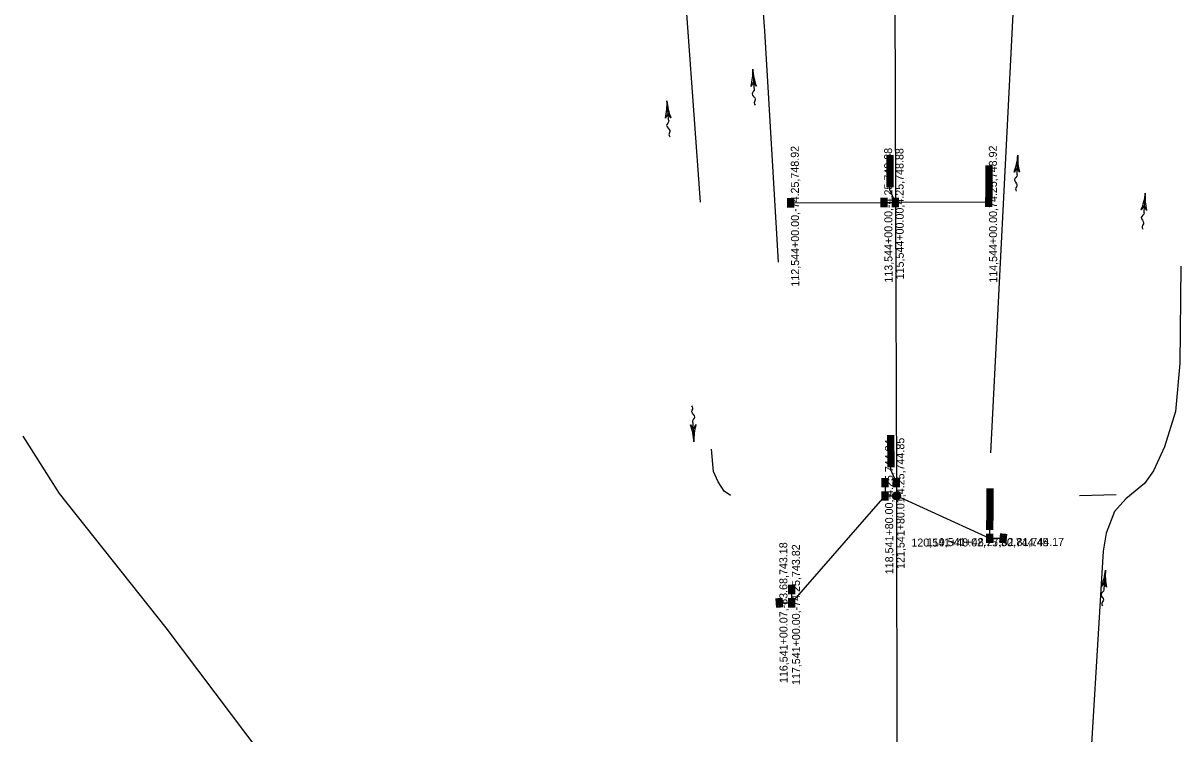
# Model space of a CAD drawing. Extents: x 593481 to 595602, y 151646 to 157396.
# Drawn here: x 593709 to 594578, y 153277 to 153810 of the extents above; entities that cross this region are included whole.
import ezdxf

# ---------------------------------------------------------------- set-up
doc = ezdxf.new("R2010")
doc.units = 0
for name, color, linetype in [('P_ALI_50_Equation', 7, 'Continuous'), ('P_DRN_Flow', 7, 'Continuous'), ('P_DRN_Inlet', 7, 'Continuous'), ('P_DRN_SS_MH', 7, 'Continuous'), ('P_DRN_SS_UG', 7, 'Continuous')]:
    doc.layers.add(name, color=color, linetype=linetype)

msp = doc.modelspace()

# ---------------------------------------------------------------- linework, layer by layer
at = {"layer": 'P_DRN_Flow'}
for p, q in [((594256.49, 153775.14), (594257.31, 153761.03)), ((594192.15, 153751.4), (594193.17, 153737.31)), ((594455.21, 153710.73), (594454.48, 153696.62)), ((594550.81, 153682.25), (594549.67, 153668.17)), ((594212.46, 153495.81), (594211.83, 153509.92)), ((594521.03, 153399.72), (594519.66, 153385.66))]:
    msp.add_line(p, q, dxfattribs=at)
for points in [[(594259.24, 153762.48), (594257.05, 153765.56), (594255.24, 153762.24)], [(594195.07, 153738.78), (594192.85, 153741.83), (594191.08, 153738.49)], [(594456.55, 153697.85), (594454.72, 153701.15), (594452.55, 153698.05)], [(594551.77, 153669.34), (594550.04, 153672.69), (594547.79, 153669.65)], [(594209.88, 153508.5), (594212.03, 153505.39), (594213.88, 153508.68)], [(594521.78, 153386.79), (594520.1, 153390.17), (594517.8, 153387.18)]]:
    msp.add_lwpolyline(points, dxfattribs=at)
for centre, start, end in [((594214.6, 153772.68), 345.59586, 3.35818), ((594298.37, 153777.6), 183.35818, 201.1205), ((594150.31, 153748.39), 346.35512, 4.11744), ((594234, 153754.41), 184.11744, 201.87976), ((594413.31, 153712.89), 339.29398, 357.0563), ((594497.11, 153708.58), 177.0563, 194.81862), ((594508.99, 153685.64), 337.60208, 355.3644), ((594592.63, 153678.86), 175.3644, 193.12672), ((594170.55, 153493.91), 2.58814, 20.35046), ((594254.38, 153497.7), 164.82582, 182.58814), ((594479.27, 153403.79), 336.67264, 354.43496), ((594562.79, 153395.65), 174.43496, 192.19728)]:
    msp.add_arc(centre, 41.96, start, end, dxfattribs=at)
for points in [[(594257.31, 153761.03), (594257.67, 153760.27), (594256.01, 153756.55), (594258.43, 153752.77), (594257.65, 153749.89), (594258.38, 153748.2)], [(594193.17, 153737.31), (594193.54, 153736.55), (594191.92, 153732.81), (594194.39, 153729.06), (594193.66, 153726.17), (594194.41, 153724.49)], [(594454.48, 153696.62), (594454.75, 153695.82), (594452.69, 153692.31), (594454.68, 153688.28), (594453.6, 153685.51), (594454.13, 153683.75)], [(594549.67, 153668.17), (594549.92, 153667.36), (594547.75, 153663.91), (594549.62, 153659.83), (594548.46, 153657.09), (594548.94, 153655.31)], [(594211.83, 153509.92), (594211.48, 153510.69), (594213.19, 153514.38), (594210.82, 153518.2), (594211.64, 153521.07), (594210.93, 153522.77)], [(594519.66, 153385.66), (594519.89, 153384.85), (594517.67, 153381.44), (594519.47, 153377.32), (594518.26, 153374.6), (594518.72, 153372.82)]]:
    msp.add_spline(points, degree=3, dxfattribs=at)
at = {"layer": 'P_DRN_Inlet'}
for p, q in [((594357.04, 153710.77), (594357.12, 153686.77)), ((594357.94, 153710.77), (594358.02, 153686.77)), ((594358.84, 153710.77), (594358.92, 153686.77)), ((594359.74, 153710.78), (594359.82, 153686.78)), ((594360.64, 153710.78), (594360.72, 153686.78)), ((594361.54, 153710.78), (594361.62, 153686.78)), ((594431.31, 153702.96), (594431.38, 153678.96)), ((594432.21, 153702.96), (594432.28, 153678.97)), ((594433.11, 153702.97), (594433.18, 153678.97)), ((594434.01, 153702.97), (594434.08, 153678.97)), ((594434.91, 153702.97), (594434.98, 153678.97)), ((594435.81, 153702.98), (594435.88, 153678.98)), ((594282.91, 153671.57), (594282.89, 153678.44)), ((594283.81, 153671.57), (594283.79, 153678.45)), ((594284.71, 153671.57), (594284.69, 153678.45)), ((594285.61, 153671.58), (594285.59, 153678.45)), ((594286.51, 153671.58), (594286.49, 153678.45)), ((594287.41, 153671.58), (594287.39, 153678.46)), ((594352.91, 153671.78), (594352.89, 153678.66)), ((594353.81, 153671.79), (594353.79, 153678.66)), ((594354.71, 153671.79), (594354.69, 153678.66)), ((594355.61, 153671.79), (594355.59, 153678.67)), ((594356.51, 153671.79), (594356.49, 153678.67)), ((594357.41, 153671.8), (594357.39, 153678.67)), ((594361.41, 153671.81), (594361.39, 153678.68)), ((594362.31, 153671.81), (594362.29, 153678.69)), ((594363.21, 153671.81), (594363.19, 153678.69)), ((594364.11, 153671.82), (594364.09, 153678.69)), ((594365.01, 153671.82), (594364.99, 153678.7)), ((594365.91, 153671.82), (594365.89, 153678.7)), ((594431.41, 153672.02), (594431.39, 153678.9)), ((594432.31, 153672.03), (594432.29, 153678.9)), ((594433.21, 153672.03), (594433.19, 153678.91)), ((594434.11, 153672.03), (594434.09, 153678.91)), ((594435.01, 153672.04), (594434.99, 153678.91)), ((594435.91, 153672.04), (594435.89, 153678.91)), ((594357.64, 153500.78), (594357.7, 153476.78)), ((594358.54, 153500.78), (594358.6, 153476.78)), ((594359.44, 153500.78), (594359.5, 153476.78)), ((594360.34, 153500.79), (594360.4, 153476.79)), ((594361.24, 153500.79), (594361.3, 153476.79)), ((594362.14, 153500.79), (594362.2, 153476.79)), ((594353.49, 153461.79), (594353.48, 153468.66)), ((594354.39, 153461.79), (594354.38, 153468.67)), ((594355.29, 153461.79), (594355.28, 153468.67)), ((594356.19, 153461.8), (594356.18, 153468.67)), ((594357.09, 153461.8), (594357.08, 153468.67)), ((594357.99, 153461.8), (594357.98, 153468.67)), ((594361.99, 153461.81), (594361.98, 153468.69)), ((594362.89, 153461.81), (594362.88, 153468.69)), ((594363.79, 153461.81), (594363.78, 153468.69)), ((594364.69, 153461.82), (594364.68, 153468.69)), ((594365.59, 153461.82), (594365.58, 153468.69)), ((594366.49, 153461.82), (594366.48, 153468.7)), ((594353.52, 153451.79), (594353.5, 153458.66)), ((594354.42, 153451.79), (594354.4, 153458.67)), ((594355.32, 153451.79), (594355.3, 153458.67)), ((594356.22, 153451.79), (594356.2, 153458.67)), ((594357.12, 153451.8), (594357.1, 153458.67)), ((594358.02, 153451.8), (594358, 153458.67)), ((594431.98, 153460.88), (594432.05, 153436.88)), ((594432.88, 153460.88), (594432.95, 153436.88)), ((594433.78, 153460.88), (594433.85, 153436.88)), ((594434.68, 153460.88), (594434.75, 153436.89)), ((594435.58, 153460.89), (594435.65, 153436.89)), ((594436.48, 153460.89), (594436.55, 153436.89)), ((594432.07, 153429.94), (594432.05, 153436.82)), ((594432.97, 153429.94), (594432.95, 153436.82)), ((594433.87, 153429.94), (594433.85, 153436.82)), ((594434.77, 153429.95), (594434.75, 153436.82)), ((594435.67, 153429.95), (594435.65, 153436.82)), ((594436.57, 153429.95), (594436.55, 153436.83)), ((594432.09, 153419.99), (594432.08, 153426.87)), ((594432.99, 153420), (594432.98, 153426.87)), ((594433.89, 153420), (594433.88, 153426.87)), ((594434.79, 153420), (594434.78, 153426.88)), ((594435.69, 153420), (594435.68, 153426.88)), ((594436.59, 153420.01), (594436.58, 153426.88)), ((594441.73, 153420.29), (594442.49, 153427.12)), ((594442.63, 153420.19), (594443.38, 153427.03)), ((594443.52, 153420.09), (594444.28, 153426.93)), ((594444.42, 153419.99), (594445.17, 153426.83)), ((594445.31, 153419.9), (594446.06, 153426.73)), ((594446.21, 153419.8), (594446.96, 153426.63)), ((594283.68, 153381.66), (594283.66, 153388.53)), ((594284.58, 153381.66), (594284.56, 153388.53)), ((594285.48, 153381.66), (594285.46, 153388.54)), ((594286.38, 153381.66), (594286.36, 153388.54)), ((594287.28, 153381.67), (594287.26, 153388.54)), ((594288.18, 153381.67), (594288.16, 153388.54)), ((594277.21, 153371.73), (594276.72, 153378.59)), ((594278.1, 153371.79), (594277.62, 153378.65)), ((594279, 153371.86), (594278.52, 153378.71)), ((594274.51, 153371.54), (594274.03, 153378.4)), ((594275.41, 153371.6), (594274.93, 153378.46)), ((594276.31, 153371.67), (594275.82, 153378.52)), ((594283.7, 153371.64), (594283.69, 153378.51)), ((594284.6, 153371.64), (594284.59, 153378.51)), ((594285.5, 153371.64), (594285.49, 153378.51)), ((594286.4, 153371.64), (594286.39, 153378.52)), ((594287.3, 153371.64), (594287.29, 153378.52)), ((594288.2, 153371.65), (594288.19, 153378.52))]:
    msp.add_line(p, q, dxfattribs=at)
for points in [[(594358.31, 153706.04), (594358.35, 153691.5), (594360.35, 153691.5), (594360.31, 153706.05)], [(594432.57, 153698.24), (594432.62, 153683.69), (594434.62, 153683.7), (594434.57, 153698.25)], [(594286.16, 153674.02), (594286.15, 153676.02), (594284.15, 153676.01), (594284.16, 153674.01)], [(594356.16, 153674.23), (594356.15, 153676.23), (594354.15, 153676.22), (594354.16, 153674.22)], [(594364.66, 153674.26), (594364.65, 153676.26), (594362.65, 153676.25), (594362.66, 153674.25)], [(594434.66, 153674.47), (594434.65, 153676.47), (594432.65, 153676.47), (594432.66, 153674.47)], [(594358.9, 153496.05), (594358.94, 153481.51), (594360.94, 153481.51), (594360.9, 153496.06)], [(594356.74, 153464.23), (594356.73, 153466.23), (594354.73, 153466.23), (594354.74, 153464.23)], [(594365.24, 153464.26), (594365.23, 153466.26), (594363.23, 153466.25), (594363.24, 153464.25)], [(594356.76, 153454.23), (594356.76, 153456.23), (594354.76, 153456.23), (594354.76, 153454.23)], [(594433.25, 153456.15), (594433.28, 153441.61), (594435.28, 153441.61), (594435.25, 153456.16)], [(594435.31, 153432.39), (594435.31, 153434.39), (594433.31, 153434.38), (594433.31, 153432.38)], [(594435.34, 153422.44), (594435.33, 153424.44), (594433.33, 153424.43), (594433.34, 153422.43)], [(594445.23, 153422.36), (594445.45, 153424.35), (594443.46, 153424.56), (594443.24, 153422.58)], [(594286.92, 153384.1), (594286.92, 153386.1), (594284.92, 153386.1), (594284.92, 153384.1)], [(594277.58, 153374.2), (594277.44, 153376.19), (594275.45, 153376.05), (594275.59, 153374.06)], [(594286.95, 153374.08), (594286.94, 153376.08), (594284.94, 153376.08), (594284.95, 153374.08)]]:
    msp.add_lwpolyline(points, close=True, dxfattribs=at)
at = {"layer": 'P_DRN_SS_MH'}
for radius in [2.98, 2.4, 1.8, 1.2, 0.6]:
    msp.add_circle((594364.26, 153455.26), radius, dxfattribs=at)
at = {"layer": 'P_DRN_SS_UG'}
for p, q in [((594362.98, 153874.26), (594363.65, 153675.25)), ((594285.15, 153675.01), (594354.86, 153675.23)), ((594354.86, 153675.23), (594363.65, 153675.25)), ((594433.65, 153675.47), (594363.65, 153675.25)), ((594363.65, 153675.25), (594364.23, 153465.25)), ((594433.65, 153675.47), (594433.64, 153678.97)), ((594355.73, 153465.23), (594355.76, 153455.23)), ((594364.23, 153465.25), (594364.26, 153455.26)), ((594285.94, 153375.08), (594355.76, 153455.23)), ((594355.76, 153455.23), (594364.26, 153455.26)), ((594434.33, 153423.44), (594364.26, 153455.26)), ((594364.26, 153455.26), (594364.78, 153204.25)), ((594529.03, 153455.96), (594501.6, 153455.43)), ((594434.31, 153434.38), (594434.3, 153436.88)), ((594434.33, 153423.44), (594434.31, 153433.38)), ((594285.94, 153375.08), (594285.94, 153385.13)), ((594276.52, 153375.13), (594285.94, 153375.08))]:
    msp.add_line(p, q, dxfattribs=at)
for points in [[(594202.46, 154341.41), (594203.42, 154336.48), (594210.24, 154297.69), (594218.23, 154243.42), (594239.55, 154107.82), (594249.28, 154001.84), (594258.41, 153896.56), (594265.3, 153803.82), (594275.52, 153630.37)], [(594127.29, 154319.04), (594123.56, 154314.77), (594121.4, 154309.67), (594122.26, 154303.59), (594124.01, 154300.18), (594133.09, 154288.52), (594143.62, 154275.25), (594149.46, 154266.36), (594156.23, 154252.07), (594161.18, 154238.26), (594165.2, 154221.74), (594171.35, 154174.68), (594181.15, 154108.35), (594187.24, 154068.13), (594193.38, 154002.92), (594217.22, 153675.55)], [(594517.63, 154267.75), (594510.41, 154267.73), (594507.44, 154265.29), (594505.7, 154263.84), (594503.23, 154258.43), (594502.33, 154251.94), (594501.27, 154245.84), (594498.53, 154222.83), (594493.59, 154169.29), (594483.93, 154111.75), (594477.34, 154030.54), (594452.1, 153826.36), (594434.68, 153487.6)], [(594363.65, 153675.25), (594359.37, 153684.77), (594359.37, 153686.77)], [(594577.51, 153627.4), (594576.83, 153554.41), (594573.55, 153518.64), (594565.18, 153492.12), (594557.02, 153474.07), (594550.25, 153464.46), (594536.33, 153453.08), (594527.79, 153443.51), (594521.45, 153427.37), (594519.33, 153413.74), (594506.98, 153211.54), (594503.05, 153118.72), (594500.35, 153076.8)], [(594231.26, 152595.76), (594237.97, 152608.05), (594241.46, 152629.09), (594238.66, 152654.63), (594233.07, 152686.73), (594216.91, 152735.08), (594189.33, 152811.49), (594166.89, 152857.49), (594145.49, 152897.16), (593987.3, 153130.11), (593816.84, 153356.32), (593736.81, 153456.97), (593709.49, 153500.13)], [(594239.95, 153455.49), (594235.13, 153458.95), (594230.63, 153465.75), (594227.08, 153473.55), (594225.72, 153490.27)], [(594364.23, 153465.25), (594359.96, 153474.78), (594359.96, 153476.78)]]:
    msp.add_lwpolyline(points, dxfattribs=at)
msp.add_arc((595163.84, -159219.3), 312643.59, 90.1318562, 90.133691, dxfattribs=at)

# ---------------------------------------------------------------- texts
at = {"layer": 'P_ALI_50_Equation'}
for s, rotation, p in [('112,544+00.00,-74.25,748.92', 90.17616, (594291.35, 153612.15)), ('114,544+00.00,74.25,748.92', 90.17616, (594439.84, 153615.07)), ('113,544+00.00,-4.25,748.88', 90.17616, (594361.34, 153615.11)), ('115,544+00.00,4.25,748.88', 90.17616, (594369.83, 153617.59)), ('118,541+80.00,-4.25,744.84', 90.13949, (594361.9, 153396.57)), ('121,541+80.01,4.25,744.85', 90.13949, (594370.39, 153400.52)), ('120,541+48.02,75.50,744.45', 0.13416, (594375.46, 153417.3)), ('119,541+48.27,82.81,744.17', 0.1342, (594387.11, 153417.58)), ('116,541+00.07,-83.68,743.18', 90.12617, (594282.65, 153315)), ('117,541+00.00,-74.25,743.82', 90.12616, (594292.08, 153313.49))]:
    msp.add_text(s, height=6, rotation=rotation, dxfattribs=at).set_placement(p)

doc.saveas('drawing.dxf')
